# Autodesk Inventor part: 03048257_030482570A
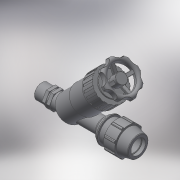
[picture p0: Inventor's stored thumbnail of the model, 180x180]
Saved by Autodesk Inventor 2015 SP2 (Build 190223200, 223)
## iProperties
Created: 2017-02
Part Number: 03048257_030482570A
Material: Generic
Description: PLASSON ANGLE SEAT VALVE 25-3/4"
Document SubType Name: Modeling
Designer: KIM
Mass: 337.755 g
Surface Area: 641.433 cm^2
Volume: 337.755 cm^3
Density: 1 g/cm^3
Appearance: Default
Author: KIM
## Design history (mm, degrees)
derived "03048-03948.ipt"
feature "Solid1::03048-03948.ipt"
tag "TaggingFeature1"
body "Solid1"
other parameters: "d2" = 25, "d4" = 7.79167, "d5" = 18.7, "d7" = 54, "d11" = 2.67143, "d13" = 120 deg, "d14" = 35, "d15" = 12 deg, "d16" = 46.98, "d18" = 1.25, "d19" = 35 deg, "d20" = 17.5 deg, "d21" = 50.22, "d23" = 0, "d25" = 360 deg, "d27" = 1.08, "d33" = 0.5, "d42" = 22.44, "d43" = 1.62, "d46" = 0.75, "d67" = 40.5, "d96" = 4.675, "d128" = 187, "d159" = 2, "d165" = 108.9, "d167" = 65.34, "d168" = 19.602, "d169" = 19.602, "d170" = 90 deg, "d171" = 70 deg, "d172" = 15.6816, "d173" = 45.738, "d174" = 45.738, "d175" = 58.806, "d176" = 135 deg, "d177" = 52.272, "d178" = 49.005, "d179" = 27.225, "d180" = 108.9, "d182" = 15.6816, "d183" = 43.1244, "d190" = 45 deg, "d191" = 37.4, "d192" = 2.42, "d193" = 4.52, "d194" = 2.26, "d195" = 57.04182, "d198" = 0, "d199" = 24.5025, "d200" = 113, "d204" = 360 deg, "d209" = 0, "d213" = 3.267, "d216" = 360 deg, "d220" = 55.539, "d221" = 3.39, "d222" = 3.39, "d223" = 6.78, "d227" = 3.39, "d229" = 0, "d230" = 0.605, "d232" = 360 deg, "d234" = 0.605, "d235" = 0.605, "d237" = 360 deg, "d239" = 0.968, "d241" = 0.605, "d249" = 26.441, "d250" = 45 deg, "d252" = 187, "d253" = 18, "d254" = 6, "d255" = 3, "d256" = 27, "d258" = 0, "d260" = 0, "d261" = 0.52882, "d265" = 0, "d266" = 121, "d_" = 25, "E_" = 54, "A_" = 121, "H_" = 187, "d224" = 113, "G_" = 26.441, "l_2" = 18, "d202" = 58.806, "d214" = 65.34, "d218" = 65.34, "d225" = 65.34, "d226" = 45.738
